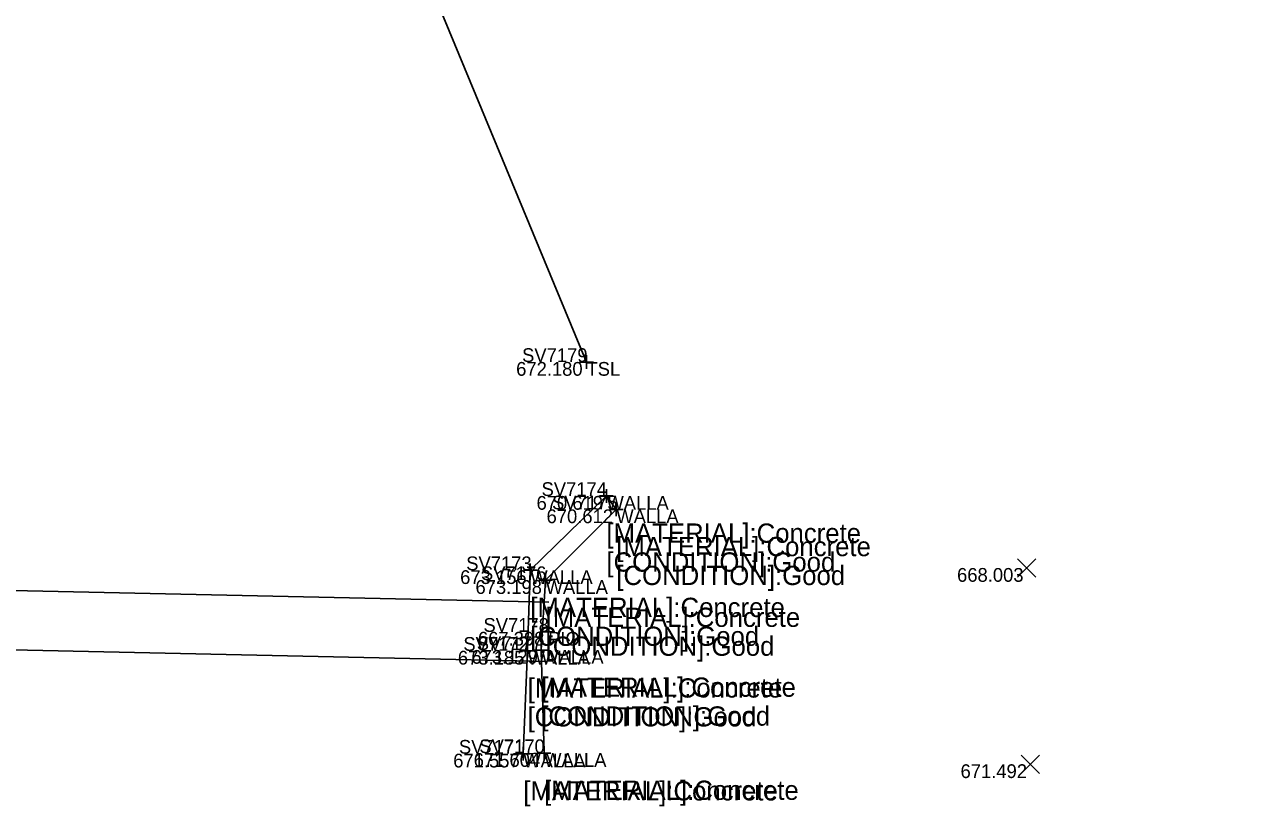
# Model space of a CAD drawing. Extents: x 1659932 to 1663108, y 619867 to 620611.
# Drawn here: x 1661449.7 to 1661539.7, y 620138.3 to 620195.1 of the extents above; entities that cross this region are included whole.
import ezdxf

# ---------------------------------------------------------------- set-up
doc = ezdxf.new("R2010")
doc.units = 0
for name, color, linetype in [('BR_X_SV_Abut', 7, 'Continuous'), ('BR_X_SV_Abut_Text', 7, 'Continuous'), ('DR_X_Culvert', 7, 'Continuous'), ('DR_X_Elev_Flow', 7, 'Continuous'), ('SV_X_Random_Point', 7, 'Continuous'), ('SV_X_Shot_Marker', 7, 'Continuous'), ('SV_X_Text', 7, 'Continuous'), ('SV_X_Text_Comment', 7, 'Continuous'), ('SV_X_Text_Elevation', 7, 'Continuous'), ('SV_X_Text_Name', 7, 'Continuous'), ('SV_X_Toe_of_Slope', 7, 'Continuous')]:
    doc.layers.add(name, color=color, linetype=linetype)

msp = doc.modelspace()

# ---------------------------------------------------------------- linework, layer by layer
at = {"layer": 'BR_X_SV_Abut'}
msp.add_lwpolyline([(1661487.525, 620142.169), (1661486.009, 620142.126), (1661486.322, 620149.608), (1661486.521, 620155.469), (1661492.058, 620160.869), (1661492.775, 620159.893), (1661487.632, 620154.749), (1661487.32, 620149.668)], close=True, dxfattribs=at)
at = {"layer": 'DR_X_Culvert'}
for p, q in [((1661220.519, 620158.972), (1661487.859, 620153.155)), ((1661220.425, 620154.64), (1661487.765, 620148.823))]:
    msp.add_line(p, q, dxfattribs=at)
at = {"layer": 'DR_X_Elev_Flow'}
for p, q in [((1661487.312, 620150.989), (1661488.312, 620150.989)), ((1661487.812, 620151.489), (1661487.812, 620150.489)), ((1661487.812, 620150.989), (1661487.812, 620150.989))]:
    msp.add_line(p, q, dxfattribs=at)
at = {"layer": 'SV_X_Random_Point'}
for p, q in [((1661521.958, 620154.963), (1661523.292, 620156.297)), ((1661521.958, 620156.297), (1661523.292, 620154.963)), ((1661522.219, 620140.688), (1661523.553, 620142.024)), ((1661522.219, 620142.024), (1661523.553, 620140.688))]:
    msp.add_line(p, q, dxfattribs=at)
at = {"layer": 'SV_X_Shot_Marker'}
for p, q in [((1661490.605, 620171.114), (1661490.605, 620170.114)), ((1661490.105, 620170.614), (1661491.105, 620170.614)), ((1661490.605, 620170.614), (1661490.605, 620170.614)), ((1661491.558, 620160.869), (1661492.558, 620160.869)), ((1661492.058, 620161.369), (1661492.058, 620160.369)), ((1661492.058, 620160.869), (1661492.058, 620160.869)), ((1661492.275, 620159.893), (1661493.275, 620159.893)), ((1661492.775, 620160.393), (1661492.775, 620159.393)), ((1661492.775, 620159.893), (1661492.775, 620159.893)), ((1661486.021, 620155.469), (1661487.021, 620155.469)), ((1661486.521, 620155.969), (1661486.521, 620154.969)), ((1661486.521, 620155.469), (1661486.521, 620155.469)), ((1661487.132, 620154.749), (1661488.132, 620154.749)), ((1661487.632, 620155.249), (1661487.632, 620154.249)), ((1661487.632, 620154.749), (1661487.632, 620154.749)), ((1661486.322, 620150.108), (1661486.322, 620149.108)), ((1661487.32, 620150.168), (1661487.32, 620149.168)), ((1661485.822, 620149.608), (1661486.822, 620149.608)), ((1661486.322, 620149.608), (1661486.322, 620149.608)), ((1661486.82, 620149.668), (1661487.82, 620149.668)), ((1661487.32, 620149.668), (1661487.32, 620149.668)), ((1661485.509, 620142.126), (1661486.509, 620142.126)), ((1661486.009, 620142.626), (1661486.009, 620141.626)), ((1661486.009, 620142.126), (1661486.009, 620142.126)), ((1661487.025, 620142.169), (1661488.025, 620142.169)), ((1661487.525, 620142.669), (1661487.525, 620141.669)), ((1661487.525, 620142.169), (1661487.525, 620142.169))]:
    msp.add_line(p, q, dxfattribs=at)
at = {"layer": 'SV_X_Toe_of_Slope'}
msp.add_lwpolyline([(1661490.605, 620170.614), (1661477.149, 620203.096), (1661498.786, 620287.484), (1661510.242, 620298.378), (1661539.687, 620302.32)], dxfattribs=at)

# ---------------------------------------------------------------- texts
at = {"layer": 'BR_X_SV_Abut_Text'}
for s, p in [('SV7174', (1661487.338, 620160.869)), ('670.619', (1661486.974, 620159.869)), ('SV7175', (1661488.106, 620159.893)), ('WALLA', (1661492.058, 620159.869)), ('670.612', (1661487.702, 620158.893)), ('WALLA', (1661492.775, 620158.893)), ('SV7173', (1661481.859, 620155.469)), ('673.156', (1661481.417, 620154.469)), ('SV7176', (1661482.93, 620154.749)), ('WALLA', (1661486.521, 620154.469)), ('673.198', (1661482.532, 620153.749)), ('WALLA', (1661487.632, 620153.749)), ('SV7172', (1661481.651, 620149.608)), ('SV7177', (1661482.626, 620149.668)), ('673.185', (1661481.252, 620148.608)), ('673.129', (1661482.236, 620148.668)), ('WALLA', (1661486.322, 620148.608)), ('WALLA', (1661487.32, 620148.668)), ('SV7171', (1661481.329, 620142.126)), ('SV7170', (1661482.813, 620142.169)), ('671.557', (1661480.913, 620141.126)), ('671.604', (1661482.403, 620141.169)), ('WALLA', (1661486.009, 620141.126)), ('WALLA', (1661487.525, 620141.169))]:
    msp.add_text(s, height=1, dxfattribs=at).set_placement(p)
at = {"layer": 'SV_X_Text'}
for s, p in [('[MATERIAL]:Concrete', (1661492.058, 620157.469)), ('[MATERIAL]:Concrete', (1661492.775, 620156.493)), ('[CONDITION]:Good', (1661492.058, 620155.369)), ('[CONDITION]:Good', (1661492.775, 620154.393)), ('[MATERIAL]:Concrete', (1661486.521, 620152.069)), ('[MATERIAL]:Concrete', (1661487.632, 620151.349)), ('[CONDITION]:Good', (1661486.521, 620149.969)), ('[CONDITION]:Good', (1661487.632, 620149.249)), ('[MATERIAL]:Concrete', (1661486.322, 620146.208)), ('[MATERIAL]:Concrete', (1661487.32, 620146.268)), ('[CONDITION]:Good', (1661486.322, 620144.108)), ('[CONDITION]:Good', (1661487.32, 620144.168)), ('[MATERIAL]:Concrete', (1661486.009, 620138.726)), ('[MATERIAL]:Concrete', (1661487.525, 620138.769))]:
    msp.add_text(s, height=1.4, dxfattribs=at).set_placement(p)
at = {"layer": 'SV_X_Text_Comment'}
for s, p in [('TSL', (1661490.605, 620169.614)), ('PIO', (1661487.812, 620149.989))]:
    msp.add_text(s, height=1, dxfattribs=at).set_placement(p)
at = {"layer": 'SV_X_Text_Elevation'}
for s, p in [('672.180', (1661485.491, 620169.614)), ('668.003', (1661517.561, 620154.63)), ('667.398', (1661482.712, 620149.989)), ('671.492', (1661517.813, 620140.356))]:
    msp.add_text(s, height=1, dxfattribs=at).set_placement(p)
at = {"layer": 'SV_X_Text_Name'}
for s, p in [('SV7179', (1661485.923, 620170.614)), ('SV7178', (1661483.113, 620150.989))]:
    msp.add_text(s, height=1, dxfattribs=at).set_placement(p)

doc.saveas('drawing.dxf')
